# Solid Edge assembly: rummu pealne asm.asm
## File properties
Author: Kadik
Template: KNOTT AKK.asm
Last saved by: Kadik
Revision: 39
Application: Solid Edge
ST_Bezeichnung1: Fekalaplap hegesztett
ST_Bezeichnung_DE: Bremsteller geschw.
ST_ArtikelNr: 6X0768.015
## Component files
rummu toru 1300kg.par
plaat.par
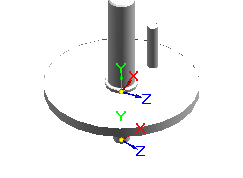
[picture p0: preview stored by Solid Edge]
